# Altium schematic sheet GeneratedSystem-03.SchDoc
size 101 x 101 mm
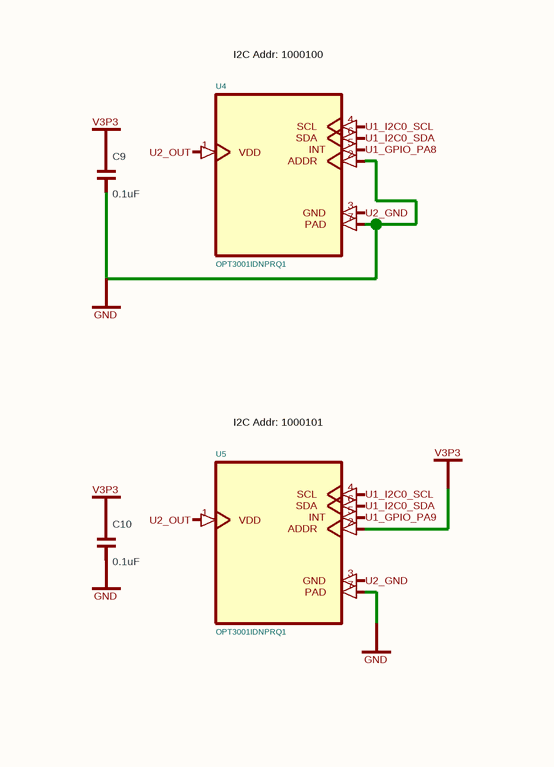
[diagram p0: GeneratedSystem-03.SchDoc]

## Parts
C9  0.1uF
C10  0.1uF
U4  (no value)
U5  (no value)

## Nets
GND: C9.2(cathode) C10.2(cathode) U4.2(ADDR) U4.7(PAD) U5.7(PAD)
V3P3: C9.1(anode) C10.1(anode) U5.2(ADDR)
U1_GPIO_PA8: U4.5(INT)
U1_GPIO_PA9: U5.5(INT)
U1_I2C0_SCL: U4.4(SCL) U5.4(SCL)
U1_I2C0_SDA: U4.6(SDA) U5.6(SDA)
U2_GND: U4.3(GND) U5.3(GND)
U2_OUT: U4.1(VDD) U5.1(VDD)

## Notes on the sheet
- (near U4) I2C Addr: 1000100
- (near U5) I2C Addr: 1000101

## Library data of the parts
C9 C10 = capacitor_down
U4 = U4
U5 = U5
